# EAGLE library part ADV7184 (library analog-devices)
Multiformat SDTV Video Decoder with Fast Switch Overlay Support Auto generated by make-symbol-device-package-bsdl.ulp Rev. 33 Source: http://www.analog.com/static/imported-files/data_sheets/ADV7184.pdf
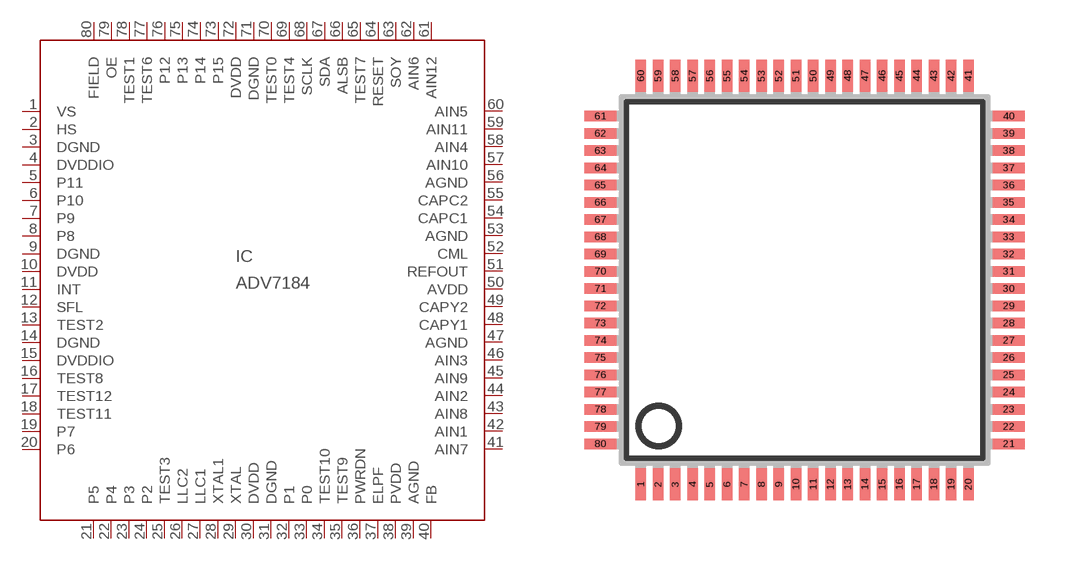
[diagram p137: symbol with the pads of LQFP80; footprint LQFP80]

Designator prefix IC

## ADV7184 (MPN: ADV7184BSTZ; OC_FARNELL: 1117101; OC_NEWARK: 31M3981)  [LQFP80]
1  VS  out
2  HS  out
3  DGND  pwr
4  DVDDIO  pwr
5  P11  out
6  P10  out
7  P9  out
8  P8  out
9  DGND  pwr
10  DVDD  pwr
11  INT  out
12  SFL  out
13  TEST2  pas
14  DGND  pwr
15  DVDDIO  pwr
16  TEST8  pas
17  TEST12  pas
18  TEST11  pas
19  P7  out
20  P6  out
21  P5  out
22  P4  out
23  P3  out
24  P2  out
25  TEST3  pas
26  LLC2  out
27  LLC1  out
28  XTAL1  out
29  XTAL  in
30  DVDD  pwr
31  DGND  pwr
32  P1  out
33  P0  out
34  TEST10  pas
35  TEST9  pas
36  PWRDN  in
37  ELPF  in
38  PVDD  pwr
39  AGND  pwr
40  FB  in
41  AIN7  in
42  AIN1  in
43  AIN8  in
44  AIN2  in
45  AIN9  in
46  AIN3  in
47  AGND  pwr
48  CAPY1  in
49  CAPY2  in
50  AVDD  pwr
51  REFOUT  out
52  CML  out
53  AGND  pwr
54  CAPC1  in
55  CAPC2  in
56  AGND  pwr
57  AIN10  in
58  AIN4  in
59  AIN11  in
60  AIN5  in
61  AIN12  in
62  AIN6  in
63  SOY  in
64  RESET  in
65  TEST7  pas
66  ALSB  in
67  SDA
68  SCLK  in
69  TEST4  pas
70  TEST0  pas
71  DGND  pwr
72  DVDD  pwr
73  P15  out
74  P14  out
75  P13  out
76  P12  out
77  TEST6  pas
78  TEST1  pas
79  OE  in
80  FIELD  out

## Footprint LQFP80 (pad centres in mm)
80 Lead LQFP_ED (SQ-80) (ST-80) Source: www.analog.com .. AD9852_b.pdf
smd 0.4 x 1.2: 1 -6.175,-7.7; 2 -5.525,-7.7; 3 -4.875,-7.7; 4 -4.225,-7.7; 5 -3.575,-7.7; 6 -2.925,-7.7; 7 -2.275,-7.7; 8 -1.625,-7.7; 9 -0.975,-7.7; 10 -0.325,-7.7; 11 0.325,-7.7; 12 0.975,-7.7; 13 1.625,-7.7; 14 2.275,-7.7; 15 2.925,-7.7; 16 3.575,-7.7; 17 4.225,-7.7; 18 4.875,-7.7; 19 5.525,-7.7; 20 6.175,-7.7; 41 6.175,7.7; 42 5.525,7.7; 43 4.875,7.7; 44 4.225,7.7; 45 3.575,7.7; 46 2.925,7.7; 47 2.275,7.7; 48 1.625,7.7; 49 0.975,7.7; 50 0.325,7.7; 51 -0.325,7.7; 52 -0.975,7.7; 53 -1.625,7.7; 54 -2.275,7.7; 55 -2.925,7.7; 56 -3.575,7.7; 57 -4.225,7.7; 58 -4.875,7.7; 59 -5.525,7.7; 60 -6.175,7.7
smd 1.2 x 0.4: 21 7.7,-6.175; 22 7.7,-5.525; 23 7.7,-4.875; 24 7.7,-4.225; 25 7.7,-3.575; 26 7.7,-2.925; 27 7.7,-2.275; 28 7.7,-1.625; 29 7.7,-0.975; 30 7.7,-0.325; 31 7.7,0.325; 32 7.7,0.975; 33 7.7,1.625; 34 7.7,2.275; 35 7.7,2.925; 36 7.7,3.575; 37 7.7,4.225; 38 7.7,4.875; 39 7.7,5.525; 40 7.7,6.175; 61 -7.7,6.175; 62 -7.7,5.525; 63 -7.7,4.875; 64 -7.7,4.225; 65 -7.7,3.575; 66 -7.7,2.925; 67 -7.7,2.275; 68 -7.7,1.625; 69 -7.7,0.975; 70 -7.7,0.325; 71 -7.7,-0.325; 72 -7.7,-0.975; 73 -7.7,-1.625; 74 -7.7,-2.275; 75 -7.7,-2.925; 76 -7.7,-3.575; 77 -7.7,-4.225; 78 -7.7,-4.875; 79 -7.7,-5.525; 80 -7.7,-6.175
